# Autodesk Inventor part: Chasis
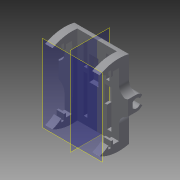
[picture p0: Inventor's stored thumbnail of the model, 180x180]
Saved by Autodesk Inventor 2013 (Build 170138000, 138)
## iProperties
Created: 2013-04
Part Number: Chasis
Material: Generic
Document SubType Name: Modeling
Designer: otrab
Density: 1 g/cm^3
Author: otrab
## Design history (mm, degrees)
sketch "Sketch1"
  geometry: L1 (-1.023, 0)-(-10, 0); L2 (35.899, 0)-(-58.357, 0); L3 (-1.023, 0)-(-25, 0); L4 (-25, 0)-(-25, 10); L5 (-10, 0)-(-10, 7.657); L6 (5.409, 7.657)-(-39.591, 7.657); L7 (-10, 0)-(-10, -7.657); L8 (0, 0)-(0, 39.302); L9 (0, 0)-(0, -39.302); A1 r 40.554 centre (-10, 0) between (0, 39.302) and (-29.591, 35.508); A2 r 29.591 centre (-39.591, 7.657) between (-10, 7.657) and (-29.591, 35.508); A3 r 40.554 centre (-10, 0) between (-29.591, -35.508) and (0, -39.302); A4 r 29.591 centre (-39.591, -7.657) between (-29.591, -35.508) and (-10, -7.657); 1 further point
  constraints: 18 end point, 8 point on circle, 5 symmetric about line, 4 centre point, 3 point on line, 2 coincident, 2 perpendicular, 1 collinear, 1 tangent, 3 other
  dimensions: "d8" = 10 distance of L3.end L4.end; "d26" = 10 distance of L1.start L6.start; "d27" = 45 distance of L6.start L6.end; "d46" = 10 distance between parallel lines of L9 L7
extrude "Extrusion1" new body sketch "Sketch1" stored distance "d10" = 55; taper "d11" = 0 deg
sketch "Sketch2"
  geometry: L1 (35.156, 33.586)-(35.156, 50.65); L2 (35.156, 50.65)-(37.588, 50.65); L3 (13.948, 33.586)-(13.948, 72.158); L4 (17.565, 72.158)-(17.565, 33.586); L5 (41.696, 72.161)-(41.696, 33.586); L6 (37.588, 50.65)-(37.588, 72.161); L7 (17.565, 6.264)-(14.012, 6.264); L8 (13.948, 72.158)-(17.565, 72.158); L9 (19.565, 39.935)-(28.605, 39.935); L10 (41.696, 33.586)-(35.156, 33.586); L11 (36.51, 29.014)-(39.896, 29.014); L12 (14.012, 29.014)-(17.565, 29.014); L13 (19.565, 15.221)-(19.565, 39.935); L14 (28.605, 39.935)-(28.605, 15.221); L15 (28.605, 15.221)-(19.565, 15.221); L16 (17.565, 29.014)-(17.565, 6.264); L17 (36.51, 6.264)-(36.51, 29.014); L18 (39.896, 6.264)-(36.51, 6.264); L19 (37.588, 72.161)-(41.696, 72.161); L20 (14.012, 6.264)-(14.012, 29.014); L21 (17.565, 33.586)-(13.948, 33.586); L22 (39.896, 29.014)-(39.896, 6.264); 1 further point
  constraints: 44 end point, 1 parallel
extrude "Extrusion2" cut sketch "Sketch2" distance "d12" = 55; taper "d13" = 0 deg
workplane "Work Plane1"
sketch "Sketch3"
  geometry: L1 (-5.928, 47.5)-(78.015, 47.5); L2 (78.015, 47.5)-(78.015, 7.5); L3 (78.015, 7.5)-(-5.928, 7.5); L4 (-5.928, 7.5)-(-5.928, 47.5); 1 further point
  constraints: 8 end point, 2 parallel, 1 horizontal, 1 perpendicular
  dimensions: "d44" = 20 distance from line of L3 point (35.508, 27.5); "d45" = 20 distance from line of point (35.508, 27.5) L1 (= d44)
extrude "Extrusion3" cut sketch "Sketch3" distance "d15" = 25; taper "d16" = 0 deg
sketch "Sketch4"
  geometry: L1 (0.133, 0.027)-(0.133, -46.715); L2 (0.133, -4.051)-(0.133, -12); L3 (0.133, -12)-(-31.867, -12); L4 (-31.867, -12)-(-31.867, -18); L5 (-31.867, -18)-(0.133, -18); L6 (0.133, -12)-(32.133, -12); L7 (32.133, -12)-(32.133, -18); L8 (32.133, -18)-(0.133, -18); L9 (0.133, -18)-(0.133, -20); L10 (0.133, -20)-(-33.867, -20); L11 (-33.867, -20)-(-33.867, -22.7); L12 (-33.867, -22.7)-(0.133, -22.7); L13 (0.133, -20)-(34.133, -20); L14 (34.133, -20)-(34.133, -22.7); L15 (34.133, -22.7)-(0.133, -22.7); L16 (-29.835, -20)-(-29.835, -18); L17 (-18.773, -18)-(-18.773, -20); L18 (-29.835, -20)-(-18.773, -20); L19 (19.039, -18)-(19.039, -20); L20 (30.101, -20)-(30.101, -18); L21 (32.133, -18)-(0.133, -18); L22 (30.101, -20)-(19.039, -20); L23 (39.302, 0)-(-39.302, 0) reference; 7 further points; 1 other entity
  constraints: 44 end point, 11 point on line, 8 symmetric about line, 7 perpendicular, 1 collinear, 1 parallel, 1 vertical, 3 other
  dimensions: "d18" = 32 distance of L2.end L3.end; "d19" = 6 distance of L3.end L4.end; "d23" = 2 distance of L5.end L9.end; "d24" = 34 distance of L9.end L10.end; "d25" = 2.7 distance of L10.end L11.end; "d51" = 12 distance between parallel lines of L23 L3
extrude "Extrusion4" cut sketch "Sketch4" distance "d21" = 55; taper "d22" = 0 deg
sketch "Sketch5"
  geometry: L1 (-0.1, -3.736)-(2.611, -3.736); L2 (-0.1, -3.736)-(-2.611, -3.736); L3 (33.867, -20)-(33.867, -22.7) reference; L4 (-2.611, 3.736)-(-4.558, 6.029); L5 (0, 9.901)-(0, -11.314); L6 (2.611, 3.736)-(4.558, 6.029); L7 (39.302, 0)-(-39.302, 0) reference; L8 (-7.558, 0)-(-7.558, -7.051); L9 (7.485, -7.051)-(7.485, -1.051); A1 r 4.558 centre (0, 0) between (-2.611, 3.736) and (-2.611, -3.736); A2 r 4.558 centre (0, 0) between (2.611, -3.736) and (2.611, 3.736); A3 r 7.558 centre (0, 0) between (7.485, -1.051) and (4.558, 6.029); A4 r 7.558 centre (0, 0) between (-4.558, 6.029) and (-7.558, 0); 5 further points; 1 other entity
  constraints: 15 end point, 8 point on circle, 4 centre point, 2 coincident, 1 collinear, 1 parallel, 1 point on line, 1 symmetric about line, 1 tangent, 1 vertical, 5 other
extrude "Extrusion7" join sketch "Sketch5" distance "d38" = 4; taper "d39" = 0 deg; dims "d52" = 11, "d53" = 0
sketch "Sketch6"
  geometry: L1 (-2.611, -3.736)-(2.611, -3.736) reference; L2 (4.558, 0)-(-39.302, 0) reference; L3 (-4.558, 0)-(4.558, 0); L4 (2.611, -3.736)-(-2.611, -3.736); A1 r 4.558 centre (0, 0) between (2.611, -3.736) and (4.558, 0) reference; A2 r 4.558 centre (0, 0) between (2.611, -3.736) and (-2.611, -3.736); 1 further point
  constraints: 6 end point, 3 point on circle, 2 collinear, 1 centre point, 1 coincident
extrude "Extrusion8" cut sketch "Sketch6" stored distance "d40" = 9; taper "d41" = 0 deg
mirror "Mirror1"
body "Solid1"
workplane "Work Plane4"
other parameters: "d28" = 12.2, "d34" = 3
